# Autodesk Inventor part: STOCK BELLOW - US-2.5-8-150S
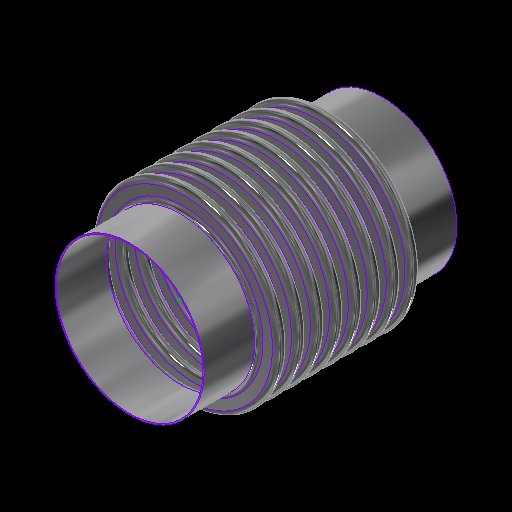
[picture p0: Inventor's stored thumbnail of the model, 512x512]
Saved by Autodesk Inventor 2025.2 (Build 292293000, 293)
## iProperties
Category: 24 GA (0.024 THICK)
RuleStatus: InUse
Created: 2024-01
Part Number: STOCK BELLOW - US-2.5-8-150S
Project: =STOCK BELLOWS: <Stock Number><SFILL>
Material: ASTM A240-304
Description: =STOCK BELLOWS: <Stock Number>, <SID_> I.D., <SOD_> O.D., <SPLY_> PLY, <Category>, <SNET_CONS> CONS.<PITCH_><STANGENT_> TANGENT<SFILL>
Document SubType Name: Sheet Metal
Designer: GS
Stock Number: U.S-2.5-8-150S
Surface Area: 1279.42 cm^2
Volume: 38.7367 cm^3
Sheet Metal Rule: Default
Appearance: STAINLESS STEEL
Mass: 312.113 g
Density: 8.05729 g/cm^3
THK: 0.036
ID: 3.500
OD: 4.250
CONS_: 2
PITCH: 0.500
TANGENT: 0.500
BELLOWS_UPSET: 0.000
d79: 1.000
d82: 1.000
d83: 26.000
d84: 24.000
d174: 8
d214: 8
STHK_: 0.024
SID_: 2.900
SOD_: 3.700
SPITCH_: 0.375
STANGENT__: 1.000
SBELLOWS_UPSET_: 0.000
SDIFF_TAN: 1.000
d252: 2
d275: 2
d287: 0.050
d289: 0.500
d290: 0.000
SOD_NECK: 2 15/16
PLY: 1
PSET: 4.178
PBAR: 1.035
COUNTER: 1.500
NET_TUBE: 3.071
CONS: 2
S_CONS: 0
NET_CONS: 2
ID_M: 88.90 mm
OD_M: 107.95 mm
THK_M: 0.91 mm
ID_U: 3.500 in
OD_U: 4.250 in
THK_U: 0.036 in
TANGENT2: 0.500
TAN_TO_TAN: 1.000 in
d80: 2.571
d81: 10
SID: 2.375
SCONS_: 8
SPITCH: 0.250
STANGENT_: 1.000
SBELLOWS_UPSET: 0.000
SNET_CONS: 8
SS_CONS: 0
SCONS: 8
d190: 8
d191: 1
d192: 1
d193: 8
d194: 0
SIZE: 2.50
PRESSURE: 150
d230: 8
STANGENT: 4.000
SPLY_: 1
d233: 8
d234: 0
d263: 2
d265: 1
d268: 2
d269: 0
d286: 2
d288: 1
d291: 2
d292: 0
SREROLL: 0.750
BLETP: 0.000 ul
PRES_Copy: 85
MATTABLE: 20 GA (0.036 THICK)
PART_NUMBER: U.S-2.5-8-150S
PITCH_: =, <SPITCH_> PITCH,
CFILL: .
SFILL: .
MESH: ,
COMP: 0.69
EXT: 0.35
LAT: 0.20
ANG: 573
ASR: 1441
LSR: 2615
ANSR: 53
PRES: 150
COMPM: 6.9
EXTM: 3.45
LATM: 2.00
ASRM: 252.362
PRESM: 10.342
LSRM: 457.965
ANSRM: 9.282
TEMPMIN: 20
TEMPMAX: 800
TEMPMINM: -7
TEMPMAXM: 427
WEIGHTM: 0.312
WEIGHT: 0.688
Author: GS
Keywords: 20 GA (0.036 THICK)
Comments: =STOCK BELLOW - <STOCK NUMBER>
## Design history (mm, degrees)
sketch "Sketch2"
  geometry: L1 (0, -177.245)-(0, 562.856) reference; L2 (45.364, 0)-(44.45, 0); L3 (48.082, -2.718)-(50.343, -2.718); L4 (48.082, -3.632)-(50.343, -3.632); L5 (50.343, -9.982)-(48.082, -9.982); L6 (50.343, -9.068)-(48.082, -9.068); L7 (45.364, -12.7)-(44.45, -12.7); L8 (48.082, 0)-(48.082, -12.7); L9 (50.343, -6.35)-(53.975, -6.35); L10 (44.45, 0)-(44.45, -12.7); L11 (20.376, 102.841)-(20.376, 101.926); L12 (58.262, 457.127)-(58.262, 349.177); L13 (58.262, 444.427)-(58.262, 336.477); L14 (93.133, -58.817)-(93.133, -71.517); L15 (118.746, -66.401)-(118.746, -66.401); L16 (50.343, -9.068)-(50.343, -9.982); L17 (48.082, -9.068)-(48.082, -9.982); L18 (48.082, -9.525)-(50.343, -9.525); L19 (53.975, 0)-(53.975, -12.7); L20 (-50.343, -9.068)-(-50.343, -9.982); L21 (-50.343, -2.718)-(-48.082, -2.718); L22 (-50.343, -3.632)-(-48.082, -3.632); L23 (-48.082, -9.068)-(-50.343, -9.068); L24 (-50.343, -9.525)-(-48.082, -9.525); L25 (-48.082, -9.982)-(-50.343, -9.982); L26 (-48.082, -9.068)-(-48.082, -9.982); L27 (-44.45, 0.653)-(-44.45, -12.047); L28 (-48.082, -6.35)-(-44.45, -6.35); L29 (-50.343, 0.653)-(-50.343, -12.7); L30 (-53.061, 0)-(-53.975, 0); L31 (-53.975, 0)-(-53.975, -12.7); L32 (-53.061, -12.7)-(-53.975, -12.7); A1 r 2.718 centre (48.082, 0) between (45.364, 0) and (48.082, -2.718); A2 r 3.632 centre (48.082, 0) between (44.45, 0) and (48.082, -3.632); A3 r 3.632 centre (50.343, -6.35) between (50.343, -9.982) and (50.343, -2.718); A4 r 2.718 centre (50.343, -6.35) between (50.343, -9.068) and (50.343, -3.632); A5 r 2.718 centre (48.082, -12.7) between (48.082, -9.982) and (45.364, -12.7); A6 r 3.632 centre (48.082, -12.7) between (48.082, -9.068) and (44.45, -12.7); A7 r 3.175 centre (50.343, -6.35) between (50.343, -9.525) and (53.518, -6.35); A8 r 3.175 centre (48.082, -12.7) between (48.082, -9.525) and (44.907, -12.7); A9 r 2.718 centre (-50.343, -12.7) between (-50.343, -9.982) and (-53.061, -12.7); A10 r 2.718 centre (-48.082, -6.35) between (-48.082, -9.068) and (-48.082, -3.632); A11 r 3.175 centre (-48.082, -6.35) between (-48.082, -9.525) and (-44.907, -6.35); A12 r 3.632 centre (-48.082, -6.35) between (-48.082, -9.982) and (-48.082, -2.718); A13 r 3.175 centre (-50.343, -12.7) between (-50.343, -9.525) and (-53.518, -12.7); A14 r 3.632 centre (-50.343, -12.7) between (-50.343, -9.068) and (-53.975, -12.7); A15 r 2.718 centre (-50.343, 0) between (-53.061, 0) and (-50.343, -2.718); A16 r 3.632 centre (-50.343, 0) between (-53.975, 0) and (-50.343, -3.632); 10 further points
  constraints: 62 end point, 38 point on circle, 20 tangent, 16 centre point, 12 parallel, 9 midpoint, 7 vertical, 6 coincident, 6 concentric, 6 point on line, 4 equal radius, 4 perpendicular, 3 horizontal, 1 collinear, 1 horizontal alignment, 10 other
  dimensions: "THK" = 0.9144 distance of L11.start L11.end; "ID" = 88.9 distance of L11.end point (20.376, 13.026); "OD" = 107.95 distance of L12.start L12.end; "PITCH" = 12.7 distance of L12.start L13.start; "TANGENT" = 12.7 distance of L14.start L14.end; "BELLOWS_UPSET" = 0 distance of L15.start L15.end; "d43" = 88.9 diameter of L10 L1 (= ID); "d44" = 107.95 diameter of L9.end L1 (= OD); "d45" = 0.9144 distance between parallel lines of L5 L6 (computed from THK, PLY); "d46" = 3.6322 radius of A3 (computed from PITCH, THK, PLY); "UPSET_PITCH" = 12.7 distance of L2.end L7.end (derived); "SIDEWALL_ANGLE" = 360 deg dimension on L3 L9 (derived); "CON_GAP" = 5.4356 distance of point (48.082, -9.068) point (48.082, -3.632) (derived); "TAN1" = 4.98728 dimension on A8 (derived); "TAN2" = 4.98728 dimension on A7 (derived); "LEG1" = 2.2606 distance of L18.start L18.end (derived); "d278" = 0.9144 distance between parallel lines of L25 L23 (derived); "d279" = 3.6322 radius of A12 (derived); "d280" = 12.7 distance of L30.end L31.end (derived); "d281" = 360 deg dimension on L21 L28 (derived); "d282" = 5.4356 distance of point (-50.343, -9.068) point (-50.343, -3.632) (derived); "d283" = 4.98728 dimension on A13 (derived); "d284" = 4.98728 dimension on A11 (derived); "d285" = 2.2606 distance of L24.start L24.end (derived); "d293" = 88.9 diameter of L27 L1 (derived); "d294" = 107.95 diameter of L31 L1 (derived)
  node "Sketch Rectangular Pattern1" dims "d31" = 25.4, "ID" = 88.9
  node "Sketch Rectangular Pattern2" dims "d39" = 25.4, "PITCH" = 12.7
revolve "CONS" stored, may be unused: angle "d48" = 90 deg
node "BELLOW MIDPLANE"
pattern_linear "Rectangular Pattern2" dims "d52" = 12.7 (= UPSET_PITCH)
sketch "Sketch5"
  geometry: C1 r 45.364 at (0, 0) reference; C2 r 44.45 at (0, 0) reference
extrude "TANGENT" new body sketch "Sketch5" distance "d53" = 12.7 (= TANGENT); taper "d54" = 0 deg
revolve "SAMETAN" stored, may be unused: angle "d65" = 90 deg
revolve "DIFFTAN" stored, may be unused: angle "d70" = 90 deg
sketch "Sketch9"
  geometry: L1 (53.319, 0)-(-53.319, 0) reference; L2 (0, -17.78)-(0, 17.78) reference; L3 (38.085, 0)-(-38.085, 0); L4 (38.085, -11.906)-(38.085, 11.906); L5 (25.385, -11.906)-(25.385, 11.906); L6 (13.15, 11.906)-(13.15, -11.906); L7 (-25.385, -11.906)-(-25.385, 11.906); L8 (-38.085, -11.906)-(-38.085, 11.906); L9 (37.291, -11.906)-(37.291, 11.906); L10 (38.085, -11.906)-(37.291, -11.906); L11 (38.085, 11.906)-(37.291, 11.906); L12 (13.546, 11.906)-(12.753, 11.906); L13 (12.753, 11.906)-(12.753, -11.906); L14 (12.753, -11.906)-(13.546, -11.906); L15 (13.546, -11.906)-(13.546, 11.906); L16 (-13.546, 11.906)-(-13.546, -11.906); L17 (-13.15, 11.906)-(-13.15, -11.906); L18 (-13.546, -11.906)-(-12.753, -11.906); L19 (-12.753, -11.906)-(-12.753, 11.906); L20 (-12.753, 11.906)-(-13.546, 11.906); L21 (-38.085, -11.906)-(-37.291, -11.906); L22 (-37.291, -11.906)-(-37.291, 11.906); L23 (-37.291, 11.906)-(-38.085, 11.906); L24 (-38.085, 11.906)-(-38.085, -11.906); L25 (38.085, -0.397)-(-38.085, -0.397); L26 (-38.085, -0.397)-(-38.085, 0.397); L27 (-38.085, 0.397)-(38.085, 0.397); L28 (38.085, 0.397)-(38.085, -0.397); L29 (-38.085, 11.906)-(38.085, 11.906); L30 (38.085, 11.906)-(38.085, 12.7); L31 (38.085, 12.7)-(-38.085, 12.7); L32 (-38.085, 12.7)-(-38.085, 11.906); L33 (38.085, -11.906)-(-38.085, -11.906); L34 (-38.085, -11.906)-(-38.085, -12.7); L35 (-38.085, -12.7)-(38.085, -12.7); L36 (38.085, -12.7)-(38.085, -11.906); 30 further points
  constraints: 68 end point, 13 midpoint, 13 parallel, 8 horizontal, 7 perpendicular, 6 equal length, 3 point on line, 2 vertical, 14 other
  dimensions: "d115" = 23.8125 distance of L4.start L4.end (derived); "d116" = 12.7 distance between parallel lines of L4 L5 (derived); "d117" = 12.23516 distance between parallel lines of L5 L6 (derived); "d125" = 38.53427 distance between parallel lines of L7 L6 (derived); "d127" = 12.7 distance between parallel lines of L8 L7 (derived); "d128" = 24.93516 distance between parallel lines of L6 L4 (derived); "d130" = 76.16943 distance between parallel lines of L8 L4 (derived); "RULER_THK" = 0.79375 distance between parallel lines of L4 L9; "d135" = 0.79375 distance of L13.end L14.end (derived); "d138" = 26.29911 distance of L13.end L16.end (derived); "d143" = 0.79375 distance of L22.end L8.end (derived); "d144" = 0.79375 distance between parallel lines of L27 L25 (derived)
extrude "RULER" join sketch "Sketch9" distance "d149" = 0.79375 (derived); taper "d150" = 0 deg
extrude "BARS" join sketch "Sketch9" distance "d151" = 0.79375 (derived); taper "d152" = 0 deg
pattern_linear "Rectangular Pattern4" dims "d155" = 26.29911 (derived)
sketch "Sketch13"
  geometry: L1 (93.149, -52.467)-(93.149, -77.867); L2 (37.44, 0)-(36.83, 0); L3 (37.44, -9.525)-(36.83, -9.525); L4 (44.304, -7.449)-(39.516, -7.449); L5 (44.304, -6.839)-(39.516, -6.839); L6 (44.304, -4.763)-(46.99, -4.763); L7 (39.516, -2.076)-(44.304, -2.076); L8 (39.516, 0)-(39.516, -9.525); L9 (36.83, 0)-(36.83, -9.525); L10 (58.254, -402.451)-(58.254, -496.431); L11 (58.254, -411.976)-(58.254, -505.956); L12 (58.254, -431.026)-(58.254, -525.006); L13 (58.254, -440.551)-(58.254, -534.531); L14 (58.254, -450.076)-(58.254, -544.056); L15 (58.254, -459.601)-(58.254, -553.581); L16 (58.254, -469.126)-(58.254, -563.106); L17 (58.254, -421.501)-(58.254, -515.481); L18 (20.376, 102.536)-(20.376, 101.926); L19 (39.516, -2.686)-(44.304, -2.686); L20 (0, -696.234)-(0, 235.664) reference; L21 (-23.752, 0)-(142.514, 0) reference; A1 r 2.076 centre (39.516, 0) between (37.44, 0) and (39.516, -2.076); A2 r 2.076 centre (39.516, -9.525) between (39.516, -7.449) and (37.44, -9.525); A3 r 2.686 centre (39.516, -9.525) between (39.516, -6.839) and (36.83, -9.525); A4 r 2.076 centre (44.304, -4.763) between (44.304, -6.839) and (44.304, -2.686); A5 r 2.686 centre (44.304, -4.763) between (44.304, -7.449) and (44.304, -2.076); A6 r 2.686 centre (39.516, 0) between (36.83, 0) and (39.516, -2.686); 6 further points; 1 other entity
  constraints: 38 end point, 15 point on circle, 9 tangent, 6 centre point, 6 parallel, 5 vertical alignment, 4 point on line, 4 vertical, 3 coincident, 3 concentric, 2 collinear, 2 equal radius, 1 horizontal, 1 perpendicular, 23 other
  dimensions: "SBELLOWS_UPSET_" = 0 distance of point (118.762, -66.401) point (118.762, -66.401); "STOTAL_THK_BELLOW__" = 0.6096 distance between parallel lines of L4 L5 (derived); "d224" = 2.68605 radius of A5 (derived); "d225" = 9.525 distance of L2.end L3.end (derived); "SSIDEWALL_ANGLE_" = 360 deg dimension on L7 L6 (derived); "SSCON_GAP_" = 4.1529 distance of point (39.516, -6.839) point (39.516, -2.686) (derived); "d235" = 73.66 diameter of L9 L20 (derived); "d236" = 93.98 diameter of L6.end L20 (derived)
  node "Sketch Rectangular Pattern4" dims "d228" = 25.4
  node "Sketch Rectangular Pattern5" dims "d229" = 25.4
revolve "SBELLOW" stored, may be unused: angle "d197" = 90 deg
pattern_linear "Rectangular Pattern5" dims "d204" = 9.525 (derived)
revolve "STANGENT" stored, may be unused: angle "d240" = 90 deg
revolve "SSAMETAN" stored, may be unused: angle "d241" = 90 deg
revolve "SDIFFTAN" stored, may be unused: angle "d246" = 90 deg
revolve "INVCON" stored, may be unused: angle "d295" = 90 deg
pattern_linear "Rectangular Pattern6" dims "d298" = 12.7 (derived)
revolve "INVTANGENT" stored, may be unused: angle "d302" = 90 deg
revolve "INVSAMETAN" stored, may be unused: angle "d307" = 90 deg
revolve "INVDIFFTAN" stored, may be unused: angle "d312" = 90 deg
sketch "ID BELLOW MOUNT CALC"
  geometry: L1 (44.45, 0)-(38.1, 0); L2 (38.1, 0)-(38.1, 12.7); L3 (38.1, 12.7)-(44.45, 12.7); L4 (44.45, 12.7)-(44.45, 0); L5 (36.513, 12.7)-(35.598, 12.7); L6 (35.598, 12.7)-(35.598, 0); L7 (35.598, 0)-(36.513, 0); L8 (36.513, 0)-(36.513, 12.7); L9 (0, -2.54)-(0, 15.24) reference; L10 (-8.89, 0)-(53.34, 0) reference; 1 further point
  constraints: 16 end point, 5 parallel, 2 collinear, 2 horizontal, 2 perpendicular
  dimensions: "d314" = 12.7 distance of L5.end L6.end (derived); "d315" = 0.9144 distance of L5.start L5.end (derived); "IG" = 1.5875 distance between parallel lines of L2 L8; "PIPE_OD" = 88.9 diameter of L4 L9; "PIPE_WALL" = 6.35 distance of L2.end L3.end; "ID_MT_BELLOW" = 71.1962 diameter of L6 L9 (derived)
revolve "CFILL" stored, may be unused: angle "d320" = 90 deg
pattern_linear "Rectangular Pattern7" dims "d323" = 12.7 (derived)
revolve "SFILL" stored, may be unused: angle "d324" = 90 deg
pattern_linear "Rectangular Pattern8" dims "d327" = 9.525 (derived)
node "STOCK BELLOW MIDPLANE"
node "BELLOW"
sketch "Sketch6"
  geometry: L1 (-12.7, 45.364)-(0, 45.364); L2 (0, 45.364)-(0, 44.45); L3 (0, 44.45)-(-12.7, 44.45); L4 (-12.7, 44.45)-(-12.7, 45.364); L5 (10.16, 0)-(-60.96, 0) reference; L6 (-38.1, -89.422)-(-38.1, 153.44) reference; 1 further point
  constraints: 8 end point, 2 parallel, 1 horizontal, 1 perpendicular
  dimensions: "d61" = 12.7 distance of L2.end L3.end (derived); "d62" = 0.9144 distance of L1.end L2.end (derived); "d63" = 88.9 diameter of L3 L5 (derived); "d64" = 25.4 distance between parallel lines of L4 L6 (derived)
sketch "Sketch12"
  geometry: 1 further point
sketch "Sketch14"
  geometry: L1 (-25.4, 37.44)-(0, 37.44); L2 (0, 37.44)-(0, 36.83); L3 (0, 36.83)-(-25.4, 36.83); L4 (-25.4, 36.83)-(-25.4, 37.44); L5 (5.08, 0)-(-30.48, 0) reference; L6 (0, -8.89)-(0, 53.34) reference; 1 further point
  constraints: 8 end point, 2 parallel, 1 collinear, 1 horizontal, 1 perpendicular
  dimensions: "d237" = 0.6096 distance of L3.end L1.start (derived); "d238" = 73.66 diameter of L3 L5 (derived); "d239" = 25.4 distance of L1.start L1.end (derived); "SOD_NECK" = 74.8792 diameter of L1 L5 (derived)
sketch "Sketch15"
  geometry: L1 (-8.89, 0)-(53.34, 0) reference; L2 (36.83, -76.2)-(37.44, -76.2); L3 (37.44, -76.2)-(37.44, -101.6); L4 (37.44, -101.6)-(36.83, -101.6); L5 (36.83, -101.6)-(36.83, -76.2); L6 (0, -124.46)-(0, 35.56) reference; 1 further point
  constraints: 8 end point, 2 parallel, 1 horizontal, 1 perpendicular
  dimensions: "d205" = 25.4 distance of L4.end L2.start (derived); "d206" = 0.6096 distance of L3.end L4.end (derived); "d207" = 73.66 diameter of L5 L6 (derived); "d208" = 76.2 distance between parallel lines of L1 L2 (derived)
node "TANGENT_"
node "SAME_TAN"
sketch "Sketch8"
  geometry: L1 (45.364, -25.4)-(44.45, -25.4); L2 (44.45, -25.4)-(44.45, -38.1); L3 (44.45, -38.1)-(45.364, -38.1); L4 (45.364, -38.1)-(45.364, -25.4); L5 (0, -48.26)-(0, 22.86) reference; L6 (-89.422, 0)-(153.44, 0) reference; 1 further point
  constraints: 8 end point, 2 parallel, 1 horizontal, 1 perpendicular
  dimensions: "d66" = 88.9 diameter of L2 L5 (derived); "TOTAL_THK_BELLOW" = 0.9144 distance of L2.end L3.end (derived); "d68" = 25.4 distance between parallel lines of L1 L6 (derived); "d69" = 12.7 distance of L1.end L2.end (derived)
node "DIFF_TAN"
node "Sketch Rectangular Pattern3" dims "d138" = 26.29911 (derived), "d141" = 25.4
node "SBELLOW_"
node "STANGENT_"
node "SSAME_TAN"
sketch "Sketch16"
  geometry: L1 (37.44, -76.2)-(36.83, -76.2); L2 (36.83, -76.2)-(36.83, -101.6); L3 (36.83, -101.6)-(37.44, -101.6); L4 (37.44, -101.6)-(37.44, -76.2); L5 (0, -124.46)-(0, 35.56) reference; L6 (-8.89, 0)-(53.34, 0) reference; 1 further point
  constraints: 8 end point, 2 parallel, 1 horizontal, 1 perpendicular
  dimensions: "SDIFF_TAN" = 25.4 distance of L3.end L1.start; "d243" = 0.6096 distance of L2.end L3.end (derived); "d244" = 76.2 distance between parallel lines of L1 L6 (derived); "d245" = 73.66 diameter of L2 L5 (derived)
node "SDIFF_TAN"
body "Solid15"
sketch "Sketch17"
  geometry: L1 (53.975, 12.7)-(53.061, 12.7); L2 (53.061, 12.7)-(53.061, 0); L3 (53.061, 0)-(53.975, 0); L4 (53.975, 0)-(53.975, 12.7); L5 (0, -2.54)-(0, 15.24) reference; L6 (-10.795, 0)-(64.77, 0) reference; 2 further points
  constraints: 8 end point, 2 parallel, 1 horizontal, 1 midpoint, 1 perpendicular, 1 point on line
  dimensions: "INVTANGENT" = 12.7 distance of L3.end L1.start (derived); "d300" = 0.9144 distance of L1.start L1.end (derived); "d301" = 107.95 diameter of L4 L5 (derived)
body "Solid16"
sketch "Sketch18"
  geometry: L1 (53.975, -25.4)-(53.061, -25.4); L2 (53.061, -25.4)-(53.061, -38.1); L3 (53.061, -38.1)-(53.975, -38.1); L4 (53.975, -38.1)-(53.975, -25.4); L5 (-10.795, 0)-(64.77, 0) reference; L6 (0, -48.26)-(0, 22.86) reference; 1 further point
  constraints: 8 end point, 2 parallel, 1 horizontal, 1 perpendicular
  dimensions: "d303" = 25.4 distance between parallel lines of L1 L5 (derived); "d304" = 12.7 distance of L3.end L1.start (derived); "d305" = 0.9144 distance of L2.end L3.end (derived); "d306" = 107.95 diameter of L4 L6 (derived)
body "Solid17"
sketch "Sketch19"
  geometry: L1 (53.975, -25.4)-(53.061, -25.4); L2 (53.061, -25.4)-(53.061, -38.1); L3 (53.061, -38.1)-(53.975, -38.1); L4 (53.975, -38.1)-(53.975, -25.4); L5 (0, -48.26)-(0, 22.86) reference; L6 (-10.795, 0)-(64.77, 0) reference; 1 further point
  constraints: 8 end point, 2 parallel, 1 horizontal, 1 perpendicular
  dimensions: "d308" = 12.7 distance of L1.end L2.end (derived); "d309" = 107.95 diameter of L4 L5 (derived); "d310" = 0.9144 distance of L2.end L3.end (derived); "d311" = 25.4 distance between parallel lines of L1 L6 (derived)
body "Solid18"
body "Solid19"
body "Solid20"
other parameters: "BMPL" = -38.1, "PSET" = 106.1212 (computed from OD, THK, PLY) [user parameter], "PBAR" = 26.29911 (= 0.570796 x PITCH + OD - ID) [user parameter; used in 1 equation term], "COUNTER" = 15 [user parameter], "NET_TUBE" = 77.99823 (computed from CONS_, PBAR, TANGENT) [user parameter], "S_CONS" = 0 [user parameter; used in 1 equation term], "ID_M" = 88.9 (= ID) [user parameter], "OD_M" = 107.95 (= OD) [user parameter], "THK_M" = 0.9144 (= THK) [user parameter], "ID_U" = 88.9 (= ID) [user parameter], "OD_U" = 107.95 (= OD) [user parameter], "THK_U" = 0.9144 (= THK) [user parameter], "D_UNITS" = 0 [user parameter], "TANGENT2" = 12.7 [user parameter], "TAN_TO_TAN" = 25.4 [user parameter], "OD_NECK" = 90.7288 [user parameter], "d79" = 25.4, "d80" = 65.29823 [user parameter], "d82" = 25.4, "d83" = 660.4, "d84" = 609.6, "sa_0" = 4, "FRAME_THK" = 0.79375 [user parameter], "CON_FLAT" = 12.23516 [user parameter], "SID" = 60.325 [user parameter], "SPITCH" = 6.35 [user parameter], "STANGENT_" = 25.4 [user parameter], "SBELLOWS_UPSET" = 0 [user parameter], "SS_CONS" = 0 [user parameter], "STAN_TO_TAN_" = 76.2 [user parameter], "d100" = 0.6096 [user parameter], "d191" = 25.4 [user parameter], "d194" = 0 [user parameter], "STANGENT" = 101.6 [user parameter], "d234" = 0 [user parameter], "SUPSET_PITCH_" = 9.525 [user parameter], "d269" = 0 [user parameter], "d287" = 1.27, "d289" = 12.7, "d290" = 0, "d292" = 0 [user parameter], "Thickness" = 3.048 (derived), "KFactor" = 4.4, "BendRadius" = 3.048 (derived), "BendReliefWidth" = 3.048 (derived), "BendReliefDepth" = 1.524 (derived), "CornerReliefSize" = 12.192 (derived), "SeamGap" = 0.00508, "MinimumRemnant" = 6.096 (derived), "TransitionRadius" = 3.048 (derived), "JacobiRadiusSize" = 3.048 (derived), "GapSize" = 3.048 (derived), "SREROLL" = 19.05 [user parameter], "CUR_STK_PITCH" = 9.525 [user parameter], "d328" = -38.1 (derived), "ASR" = 14410 [user parameter], "LSR" = 26150 [user parameter], "BLETP" = 0 [user parameter], "ASRM" = 2523.6233 [user parameter], "PRESM" = 103.41975 [user parameter], "LSRM" = 4579.6495 [user parameter], "ANSRM" = 92.8189 [user parameter], "TEMPMIN" = 2664.83333 [user parameter], "TEMPMAX" = 6998.16667 [user parameter], "TEMPMINM" = 2664.83333 [user parameter], "TEMPMAXM" = 6998.16667 [user parameter], "WEIGHT" = 3.12113 [user parameter], "WEIGHTM" = 0.00312 [user parameter]
